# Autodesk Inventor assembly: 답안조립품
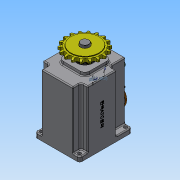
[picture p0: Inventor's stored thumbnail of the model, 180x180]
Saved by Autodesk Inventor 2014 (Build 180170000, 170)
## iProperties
Created: 2017-12
Part Number: 답안조립품
Document SubType Name: Assembly
Designer: 학생용
Author: 학생용
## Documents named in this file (17)
- C:\Users\학생용\Desktop\371207V1024\답안조립품.iam
- C:\Users\학생용\Desktop\371207V1024\본체.ipt
- C:\Users\학생용\Desktop\371207V1024\부시.ipt
- C:\Users\학생용\Desktop\371207V1024\오일 실 17 32 8.ipt
- C:\Users\학생용\Desktop\371207V1024\커버.ipt
- C:\Users\학생용\Desktop\371207V1024\오일 실 8 22 7.ipt
- C:\Users\학생용\Desktop\371207V1024\베어링 608.ipt
- C:\Users\학생용\Desktop\371207V1024\베어링 6003.ipt
- C:\Users\학생용\Desktop\371207V1024\메인축.ipt
- C:\Users\학생용\Desktop\371207V1024\서브축.ipt
- C:\Users\학생용\Desktop\371207V1024\키 5 x 5 x 18.ipt
- C:\Users\학생용\Desktop\371207V1024\스프로킷.ipt
- C:\Users\학생용\Desktop\371207V1024\멈춤나사 M3x8.ipt
- C:\Users\학생용\Desktop\371207V1024\슬라이더.ipt
- C:\Users\학생용\Desktop\371207V1024\볼트 M4 x 10.ipt
- C:\Users\학생용\Desktop\371207V1024\상부 캡.ipt
- C:\Users\학생용\Desktop\371207V1024\가변스프링.ipt
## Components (1 placed, 1 different names)
1. 가변스프링:1
